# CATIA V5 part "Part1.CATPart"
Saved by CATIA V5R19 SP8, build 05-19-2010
Part number: Part1
Publications: "PointE", "Point.2", "PointF", "PointB", "PointA", "Point.7", "Point.8", "Point.9", "Plan yz"
Bounding box of the stored display mesh (mm): x 0 to 0, y -80 to 200, z -120 to 80
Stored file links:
  C:\Users\rcousturie\Desktop\EU_thinkMotion\iao\IAO_MMS_Groupe1\flamrini\Lamrini_projet_IAO2011\Lamrini_projet_IAO2011\projet_iao_traindatterrissage\projet_iao_traindatterrissage\Part1.CATPart
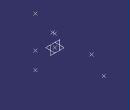
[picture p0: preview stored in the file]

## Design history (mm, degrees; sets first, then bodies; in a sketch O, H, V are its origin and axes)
Set1
  Point1 "PointE": (0, 0, 0)
  Point2 "Pointb": (0, 0, 50), relative to Point1
  Point3 "PointF": (0, 200, 0), relative to Point1
  Point4 "PointB": (0, -80, -50), relative to Point1
  Point5 "PointA": (0, -80, 80), relative to Point1
  Point6: (0, -80, -120), relative to Point1
  Point7: (0, -10, 50), relative to Point1
  Point8: (0, 150, 50), relative to Point1
Body1 (main body)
